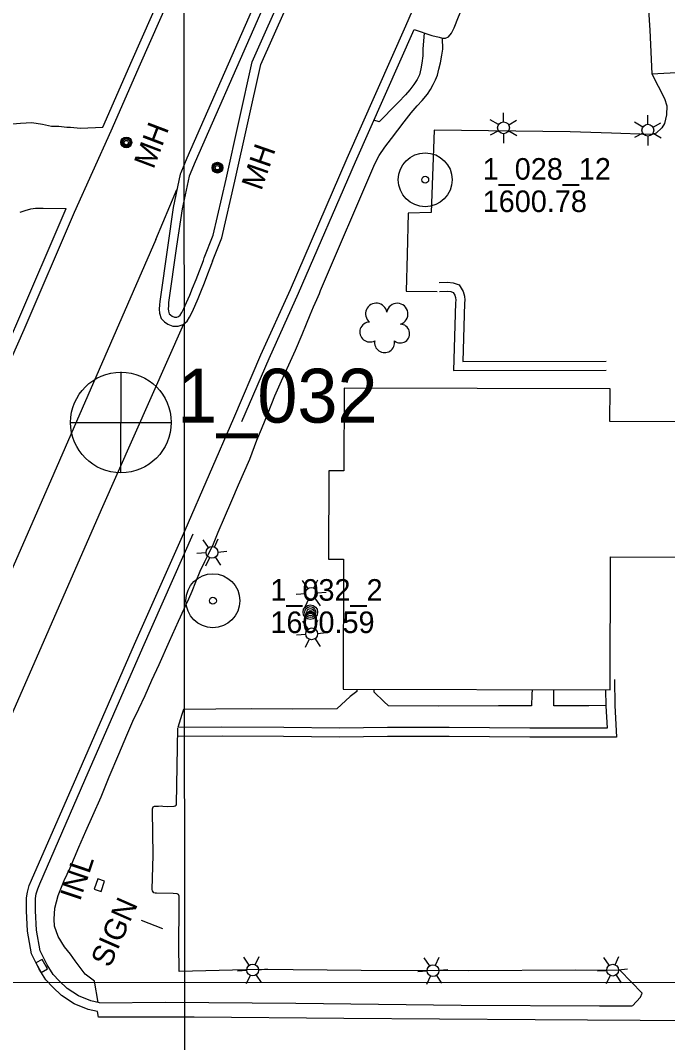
# Model space of a CAD drawing. Extents: x 189384 to 193282, y 256970 to 260388.
# Drawn here: x 190601.7 to 190781.8, y 257994.7 to 258279 of the extents above; entities that cross this region are included whole.
import ezdxf

# ---------------------------------------------------------------- set-up
doc = ezdxf.new("R2010")
doc.units = 0
for name, color, linetype in [('E_DRN_Grate', 7, 'Continuous'), ('E_DWY', 7, 'Continuous'), ('E_LAND_Vegetation', 7, 'Continuous'), ('E_MAP_GridLines', 7, 'Continuous'), ('E_MAP_Limits', 7, 'Continuous'), ('E_MAP_PassPoints', 7, 'Continuous'), ('E_MISCPROP', 7, 'Continuous'), ('E_MISCPROP_HvyLine', 7, 'Continuous'), ('E_MISCPROP_Railing', 7, 'Continuous'), ('E_PATH_Sidewalk', 7, 'Continuous'), ('E_RDWY', 7, 'Continuous')]:
    doc.layers.add(name, color=color, linetype=linetype)

# ---------------------------------------------------------------- blocks, each defined once
blk = doc.blocks.new('PP')
at = {"layer": 'E_MAP_PassPoints'}
for radius in [7.5, 0.96]:
    blk.add_circle((0, 0), radius, dxfattribs=at)
blk = doc.blocks.new('PP_2')
at = {"layer": 'E_MAP_PassPoints'}
for radius in [7.5, 0.96]:
    blk.add_circle((0, 0), radius, dxfattribs=at)
blk = doc.blocks.new('PHOTOC')
at = {"layer": 'E_MAP_Limits'}
for p, q in [((0.12, 14.06), (0.06, -13.8)), ((-13.79, 0.03), (14.12, 0.01))]:
    blk.add_line(p, q, dxfattribs=at)
blk.add_circle((0.17, 0.03), 14, dxfattribs=at)
blk = doc.blocks.new('MHO_1')
at = {"layer": 'E_DRN_Grate'}
for centre, radius in [((0.04, -0.06), 1.5), ((0.04, -0.06), 1.22), ((0.04, -0.07), 0.968), ((0.01, -0.08), 0.605)]:
    blk.add_circle(centre, radius, dxfattribs=at)
blk = doc.blocks.new('MHO_3')
at = {"layer": 'E_DRN_Grate'}
for centre, radius in [((0.04, -0.06), 1.5), ((0.04, -0.06), 1.22), ((0.04, -0.07), 0.968), ((0.01, -0.08), 0.605)]:
    blk.add_circle(centre, radius, dxfattribs=at)
blk = doc.blocks.new('LTP_6')
at = {"layer": 'E_MISCPROP'}
for p, q in [((-0.8, 1.43), (-2, 3.73)), ((0.9, 1.42), (2.27, 3.65)), ((-1.63, 0.07), (-4.24, 0.14)), ((-0.88, -1.42), (-2.24, -3.61)), ((0.76, -1.47), (2, -3.65)), ((1.64, -0.02), (4.16, -0.09))]:
    blk.add_line(p, q, dxfattribs=at)
blk.add_circle((0, 0), 1.64, dxfattribs=at)
blk = doc.blocks.new('TREE_8')
at = {"layer": 'E_LAND_Vegetation'}
for centre, radius, start, end in [((-1.47, 4.28), 2.78, 1.3947, 209.1677), ((-4.47, 0.2), 2.78, 78.0717, 279.0828), ((3.57, 2.42), 2.97, 278.4238, 139.6577), ((-2.01, -4.2), 2.61, 140.7799, 358.7125), ((3.46, -3.43), 2.97, 196.0746, 79.0479)]:
    blk.add_arc(centre, radius, start, end, dxfattribs=at)
blk = doc.blocks.new('PHOTOC_1')
at = {"layer": 'E_MAP_Limits'}
for p, q in [((0.12, 14.06), (0.06, -13.8)), ((-13.79, 0.03), (14.12, 0.01))]:
    blk.add_line(p, q, dxfattribs=at)
blk.add_circle((0.17, 0.03), 14, dxfattribs=at)
blk = doc.blocks.new('INLT_2')
at = {"layer": 'E_MISCPROP_Railing'}
blk.add_lwpolyline([(3, -2), (3, 0), (0, 0), (0, -2), (3, -2)], dxfattribs=at)
blk = doc.blocks.new('INLT_3')
at = {"layer": 'E_MISCPROP_Railing'}
blk.add_lwpolyline([(3, -2), (3, 0), (0, 0), (0, -2), (3, -2)], dxfattribs=at)
blk = doc.blocks.new('INL_3')
at = {"layer": 'E_MISCPROP_Railing'}
blk.add_text('INL', height=6, rotation=0.0001, dxfattribs=at).set_placement((-5.79, -2.75))
blk = doc.blocks.new('POLE_3')
at = {"layer": 'E_MISCPROP'}
for centre, radius in [((-0.01, 0.02), 2.02), ((-0.01, 0.03), 1.52), ((0, -0.01), 1.01), ((0, 0), 0.502)]:
    blk.add_circle(centre, radius, dxfattribs=at)
blk = doc.blocks.new('LTP_3')
at = {"layer": 'E_MISCPROP'}
for p, q in [((-0.8, 1.43), (-2, 3.73)), ((0.9, 1.42), (2.27, 3.65)), ((-1.64, 0.07), (-4.24, 0.14)), ((-0.88, -1.42), (-2.24, -3.61)), ((0.76, -1.47), (2, -3.65)), ((1.64, -0.02), (4.16, -0.09))]:
    blk.add_line(p, q, dxfattribs=at)
blk.add_circle((0, 0), 1.64, dxfattribs=at)
blk = doc.blocks.new('SIGN_3')
at = {"layer": 'E_MISCPROP'}
blk.add_text('SIGN', height=6, rotation=0.0001, dxfattribs=at).set_placement((-9.6, -3.01))

msp = doc.modelspace()

# ---------------------------------------------------------------- linework, layer by layer
at = {"layer": 'E_DWY'}
for points in [[(190711.24, 258276.48), (190716.2, 258274.86), (190718.24, 258274.36), (190719.12, 258274.13), (190719.96, 258274.1), (190720.85, 258274.5), (190721.65, 258275.48), (190722.43, 258276.98), (190723.63, 258279.98), (190730.47, 258296.26), (190731.03, 258297.66), (190732.5, 258301.06), (190732.6, 258302.29), (190732.29, 258303.32), (190731.6, 258304.03), (190730.99, 258304.56), (190730.42, 258305.08), (190725.78, 258310.13)], [(190777.42, 258264.13), (190780.95, 258257.32), (190781.61, 258255.24), (190781.5, 258252.73), (190780.93, 258250.39), (190780.22, 258249.18), (190778.63, 258247.63), (190777.7, 258247.34), (190776.69, 258247.31), (190766.21, 258247.68), (190754.67, 258248.01), (190716.82, 258248.46), (190716.02, 258225.63), (190709.55, 258225.37), (190709.29, 258213.87), (190709.07, 258203.73), (190717.67, 258203.64)], [(190571.41, 258243.16), (190582.79, 258247.78), (190585.57, 258248.49), (190588.91, 258249.27), (190592.75, 258249.91), (190595.45, 258250.07), (190598.48, 258250.18), (190601.73, 258250.45), (190604.81, 258250.59), (190607.83, 258250.14), (190610.29, 258249.63), (190612.32, 258249.6), (190614.56, 258249.35), (190615.62, 258249.32), (190618.35, 258249.03), (190624.63, 258249.31)], [(190601.57, 258225.7), (190603.01, 258226.17), (190604.57, 258226.6), (190605.85, 258226.77), (190606.82, 258226.83), (190607.51, 258226.82), (190607.95, 258226.8), (190614.38, 258226.68)], [(190718.2, 258206.15), (190720.55, 258206.25), (190722.08, 258206.04), (190723.76, 258205.45), (190724.85, 258203.66), (190725.24, 258202.36), (190725.31, 258201.21), (190725.28, 258200.4), (190724.81, 258184.15), (190764.69, 258184.27)], [(190718.3, 258203.65), (190720.43, 258203.74), (190721.49, 258203.6), (190722.09, 258203.38), (190722.55, 258202.63), (190722.76, 258201.92), (190722.81, 258201.18), (190722.78, 258200.49), (190722.24, 258181.64), (190764.7, 258181.77)], [(190766.98, 258095.69), (190767.14, 258088.47), (190767.6, 258079.68), (190743.41, 258079.62), (190721.01, 258079.82), (190703.85, 258079.82), (190690.44, 258079.64), (190674.92, 258079.86), (190657.77, 258079.94), (190645.55, 258079.8)], [(190764.54, 258092.83), (190764.64, 258088.38), (190764.96, 258082.17), (190743.42, 258082.12), (190721.02, 258082.32), (190703.84, 258082.32), (190690.44, 258082.14), (190674.94, 258082.36), (190657.76, 258082.44), (190645.52, 258082.3)], [(190772.02, 258004.91), (190774.23, 258007.32), (190774.68, 258008.42), (190768.61, 258014.78), (190756.11, 258014.88), (190726.42, 258014.7), (190696.51, 258014.76), (190668.12, 258015), (190645.85, 258014.48), (190645.75, 258022.01), (190645.86, 258032.13), (190645.82, 258035.46), (190645.62, 258035.85), (190645.33, 258036.03), (190644.19, 258036.19), (190639.58, 258036.23), (190639.16, 258036.26), (190638.78, 258036.37), (190638.46, 258036.9), (190638.35, 258037.26), (190638.61, 258046.84), (190638.41, 258059.14), (190638.45, 258059.74), (190638.63, 258060.23), (190639, 258060.43), (190639.44, 258060.49), (190640.11, 258060.5), (190640.82, 258060.51), (190641.31, 258060.48), (190642.62, 258060.35), (190644.41, 258060.42), (190644.7, 258060.51), (190645.03, 258060.75), (190645.12, 258061.06), (190645.52, 258082.2)]]:
    msp.add_lwpolyline(points, dxfattribs=at)
at = {"layer": 'E_MAP_GridLines'}
for p, q in [((190647.76, 257511.45), (190646.69, 259011.44)), ((190648.11, 257011.45), (190647.05, 258511.45)), ((189647.41, 258010.74), (191647.4, 258012.16)), ((190147.4, 258011.09), (191647.4, 258012.16))]:
    msp.add_line(p, q, dxfattribs=at)
at = {"layer": 'E_MISCPROP'}
msp.add_line((190641.34, 258026.3), (190635.4, 258028.63), dxfattribs=at)
at = {"layer": 'E_MISCPROP_HvyLine'}
msp.add_lwpolyline([(190691.47, 258093.01), (190765.78, 258092.82), (190765.87, 258129.81), (190793.45, 258129.75), (190793.55, 258167.4), (190765.75, 258167.47), (190765.77, 258176.51), (190691.75, 258176.7), (190691.69, 258153.73), (190687.5, 258153.74), (190687.44, 258129.21), (190691.57, 258129.2)], close=True, dxfattribs=at)
at = {"layer": 'E_PATH_Sidewalk'}
for points in [[(190685.22, 258203.9), (190700.32, 258239.14), (190701.47, 258241.41), (190703.08, 258243.74), (190704.94, 258246.13), (190706.69, 258248.54), (190708.46, 258250.84), (190710.41, 258253.34), (190712.09, 258255.28), (190713.52, 258256.79), (190715, 258258.54), (190715.82, 258259.78), (190716.58, 258261.16), (190717.22, 258262.52), (190717.7, 258263.82), (190718.15, 258265.47), (190718.62, 258267.26), (190718.99, 258269.33), (190719.24, 258271.01), (190719.12, 258274.13)], [(190714.04, 258275.57), (190713.67, 258271.04), (190713.66, 258269.15), (190713.4, 258267.15), (190713.15, 258265.58), (190712.71, 258263.92), (190712.11, 258262.6), (190711.2, 258261.19), (190710.06, 258259.69), (190708.82, 258258.31), (190706.87, 258256.32), (190704.71, 258254.04), (190703.2, 258252.49), (190702.39, 258251.66), (190701.87, 258251.19), (190701.75, 258251.05), (190701.52, 258250.85), (190700.06, 258251.32)], [(190623.32, 258005.87), (190622.26, 258011.76), (190619.67, 258013.76), (190618.57, 258015.21), (190616.91, 258017.4), (190615.61, 258019.32), (190613.96, 258021.34), (190612.18, 258024.2), (190611.11, 258027.12), (190611.01, 258029.05), (190611.23, 258032.09), (190612.18, 258035.61), (190613.84, 258039.81), (190615.48, 258043.3), (190617.92, 258049.07), (190619.84, 258053.52), (190621.81, 258057.89), (190624.15, 258063.08), (190626.39, 258068.66), (190629.02, 258074.88), (190631.28, 258080.25), (190632.95, 258084.08), (190634.6, 258087.53), (190636.34, 258091.2), (190638.26, 258095.47), (190640.25, 258099.82), (190643.16, 258106.39), (190645.69, 258111.95), (190647.24, 258115.33), (190647.71, 258116.36), (190648.5, 258118.16), (190649.43, 258120.26), (190650.47, 258122.84), (190651.69, 258125.79), (190652.98, 258128.5), (190654.04, 258130.54), (190655.38, 258133.47), (190656.68, 258136.67), (190658.43, 258140.75), (190660.54, 258145.52), (190662.32, 258149.86), (190665.5, 258156.99), (190667.46, 258162.29), (190668.72, 258165.35), (190670.62, 258169.9), (190672.47, 258174.61), (190674.34, 258178.81), (190676.34, 258183.22), (190678.2, 258187.31), (190680.05, 258191.66), (190681.28, 258194.6), (190682.3, 258197.15), (190682.77, 258198.28), (190683.23, 258199.31), (190684.12, 258201.42), (190684.87, 258203.1), (190685.22, 258203.9)], [(190695.3, 258093), (190695.3, 258092.34), (190693.4, 258090.93), (190689.77, 258087.55), (190677.5, 258087.48), (190665.94, 258087.52), (190656.01, 258087.44), (190647.02, 258087.33), (190646.57, 258085.97), (190645.52, 258082.3)], [(190744.07, 258092.88), (190744.01, 258091.5), (190743.94, 258088.35), (190734.77, 258088.34), (190717.94, 258088.31), (190704.15, 258088.41), (190702.83, 258089.57), (190700.14, 258092.18), (190700.13, 258092.99)], [(190764.64, 258088.48), (190759.9, 258088.4), (190750.13, 258088.39), (190750.16, 258091.81), (190750.16, 258092.86)]]:
    msp.add_lwpolyline(points, dxfattribs=at)
at = {"layer": 'E_RDWY'}
for points in [[(190616.68, 258225.7), (190626.92, 258248.31), (190635.07, 258266.98), (190648.32, 258297.01), (190666.22, 258338.37), (190675.94, 258361.41), (190677.12, 258364.96), (190677.58, 258367.44), (190677.79, 258369.25), (190677.84, 258370.35), (190676.64, 258376.89), (190675.7, 258379.42), (190674.33, 258381.46), (190672.75, 258383.67), (190670.75, 258385.6), (190668.18, 258387.61), (190665.38, 258389), (190662.69, 258390.36), (190659.88, 258391.68), (190647.05, 258398.72), (190637.72, 258402.65), (190626.82, 258407.13), (190619.98, 258409.92), (190619.19, 258407.54)], [(190624.63, 258249.31), (190632.78, 258267.99), (190646.03, 258298.02), (190663.93, 258339.35), (190673.6, 258362.29), (190674.69, 258365.58), (190675.1, 258367.82), (190675.3, 258369.45), (190675.33, 258370.17), (190674.22, 258376.22), (190673.46, 258378.27), (190672.28, 258380.04), (190670.85, 258382.03), (190669.11, 258383.71), (190666.84, 258385.48), (190664.26, 258386.76), (190661.6, 258388.12), (190658.75, 258389.45), (190645.96, 258396.47), (190636.76, 258400.34), (190625.88, 258404.82), (190619.19, 258407.54)], [(190655.15, 258212.08), (190657.73, 258218.58), (190661.37, 258234.29), (190668.54, 258266.74), (190707.08, 258353.21), (190709.49, 258358.51), (190709.98, 258360.4), (190709.94, 258361.95), (190709.15, 258363.81), (190707.97, 258364.83), (190706.07, 258365.65), (190704.5, 258365.34), (190703.21, 258364.77), (190702.47, 258363.94), (190702, 258363.33), (190701.36, 258362.46), (190687.77, 258331.38), (190664.25, 258277.63), (190647.97, 258240.66), (190646.3, 258236.67), (190646.16, 258236.23)], [(190708.95, 258277.49), (190723.47, 258311.08), (190731.29, 258330.13), (190738.5, 258348.57), (190742.07, 258358.33), (190743.07, 258360.52), (190744.03, 258362.17), (190744.95, 258363.27), (190745.84, 258364.05), (190746.7, 258364.72), (190748.34, 258365.52), (190749.54, 258365.92), (190750.87, 258366.24), (190751.94, 258366.49), (190753.53, 258366.46), (190754.66, 258366.35), (190755.63, 258366.15), (190756.81, 258365.89), (190767.32, 258362.42), (190769.01, 258361.93), (190772.39, 258360.68), (190771.52, 258358.34)], [(190652.83, 258213), (190655.33, 258219.33), (190658.93, 258234.84), (190666.15, 258267.53), (190704.8, 258354.24), (190707.13, 258359.35), (190707.47, 258360.69), (190707.45, 258361.41), (190707.08, 258362.3), (190706.63, 258362.69), (190705.8, 258363.04), (190705.25, 258362.94), (190704.71, 258362.7), (190704.4, 258362.35), (190704.01, 258361.83), (190703.54, 258361.2), (190690.06, 258330.38), (190666.54, 258276.62), (190650.27, 258239.67), (190648.61, 258235.7)], [(190776.13, 258287.7), (190776.85, 258276.31), (190777.42, 258264.13)], [(190676.79, 258204.15), (190692.6, 258240.68), (190708.95, 258277.49)], [(190679.08, 258203.16), (190694.89, 258239.67), (190711.24, 258276.48)], [(190777.42, 258264.16), (190807.79, 258265.84), (190827.61, 258267.03), (190880.57, 258269.53), (190910.27, 258270.75), (190933.63, 258272.26), (190976.88, 258274.04), (190985.13, 258274.24)], [(190646.16, 258236.23), (190644.18, 258227.02), (190642.66, 258216.55), (190640.44, 258200.88), (190640.34, 258199.89), (190640.24, 258198.69), (190640.38, 258197.61), (190640.82, 258196.12), (190641.76, 258195.19), (190642.66, 258194.51), (190644.05, 258193.99), (190645.55, 258193.99), (190646.92, 258194.44), (190648.04, 258195.41), (190648.75, 258196.48), (190649.45, 258197.84), (190650.21, 258199.56), (190651.09, 258201.63), (190651.91, 258203.56), (190652.88, 258206.06), (190653.82, 258208.5), (190654.46, 258210.19), (190654.93, 258211.41), (190655.19, 258212.19)], [(190648.61, 258235.7), (190646.64, 258226.58), (190645.14, 258216.19), (190642.92, 258200.57), (190642.83, 258199.67), (190642.76, 258198.76), (190642.84, 258198.12), (190643.03, 258197.44), (190643.4, 258197.09), (190643.88, 258196.72), (190644.5, 258196.49), (190645.15, 258196.49), (190645.66, 258196.66), (190646.15, 258197.08), (190646.6, 258197.75), (190647.19, 258198.92), (190647.91, 258200.55), (190648.79, 258202.61), (190649.59, 258204.5), (190650.55, 258206.97), (190651.49, 258209.39), (190652.12, 258211.08), (190652.58, 258212.27), (190652.83, 258213)], [(190639.31, 258218.07), (190645.21, 258231.98)], [(190486.34, 257929.3), (190500.99, 257962.31), (190519.93, 258005.2), (190540.88, 258052.68), (190557.27, 258090.57), (190575.92, 258132.39), (190589.56, 258163.44), (190602.68, 258193.06), (190616.68, 258225.7)], [(190498.7, 257963.32), (190517.65, 258006.21), (190538.59, 258053.68), (190554.98, 258091.58), (190573.63, 258133.41), (190587.27, 258164.44), (190600.39, 258194.06), (190614.38, 258226.68)], [(190639.31, 258218.07), (190609.41, 258149.39), (190580.27, 258083.06), (190547.78, 258009.13), (190519.09, 257944.03), (190494.25, 257887.28), (190465.55, 257822.08), (190442.19, 257769.07), (190419.9, 257718.5), (190394.49, 257660.93), (190374.24, 257614.8), (190349, 257556.99), (190323.12, 257498.57), (190298.43, 257442.39), (190276.94, 257393.85), (190259.86, 257355.22)], [(190647.5, 258137.19), (190661.04, 258168.43), (190668.6, 258186.03), (190676.8, 258204.19)], [(190663.33, 258167.44), (190670.89, 258185.02), (190679.08, 258203.16)], [(190647.06, 258194.52), (190624.13, 258142.92), (190594.92, 258076.29), (190570.69, 258021.28), (190551.11, 257977.35), (190533.78, 257937.86), (190511.8, 257887.72), (190488.43, 257834.81), (190463.86, 257779), (190437.37, 257718.32), (190410.84, 257658.32), (190384.1, 257597.28), (190367.03, 257558.94), (190342.84, 257503.57), (190317.05, 257445.11), (190294.43, 257394.4)], [(190623.12, 258003.35), (190620.53, 258003.93), (190616.63, 258005.47), (190613.13, 258007.77), (190610.64, 258010.1), (190608.76, 258012.12), (190606.91, 258015.08), (190604.77, 258019.43), (190603.62, 258025.68), (190603.33, 258031.32), (190603.39, 258034.96), (190603.62, 258036.57), (190604.13, 258038.35), (190604.78, 258039.88), (190617.34, 258068.71), (190633.44, 258105.56), (190647.5, 258137.19)], [(190623.66, 258005.8), (190621.26, 258006.33), (190617.79, 258007.7), (190614.68, 258009.74), (190612.41, 258011.87), (190610.75, 258013.65), (190609.1, 258016.29), (190607.16, 258020.23), (190606.11, 258025.97), (190605.83, 258031.36), (190605.89, 258034.76), (190606.07, 258036.05), (190606.49, 258037.51), (190607.07, 258038.89), (190619.63, 258067.71), (190635.73, 258104.55), (190649.78, 258136.18)], [(190816.23, 258011.98), (190816.28, 258000.29), (190788.69, 258000.79), (190744.97, 258001), (190691.66, 258001.43), (190650.06, 258001.77), (190623.43, 258001.74), (190623.12, 258003.35)], [(190623.66, 258005.8), (190641.97, 258005.93), (190678.31, 258005.7), (190724.3, 258005.15), (190762.8, 258004.92), (190771.93, 258004.91)]]:
    msp.add_lwpolyline(points, dxfattribs=at)

# ---------------------------------------------------------------- block references
at = {"layer": 'E_DRN_Grate', "xscale": 1.0000015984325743, "yscale": 1.0000015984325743, "rotation": 69.24803270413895}
msp.add_blockref('MHO_1', (190631.06, 258245.07), dxfattribs=at)
at = {"layer": 'E_DRN_Grate', "rotation": 70.86176371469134}
msp.add_blockref('MHO_3', (190656.42, 258238.04), dxfattribs=at)
at = {"layer": 'E_LAND_Vegetation', "xscale": 1.0000013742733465, "yscale": 1.0000013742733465, "rotation": 90.72455191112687}
msp.add_blockref('TREE_8', (190703.16, 258193.87), dxfattribs=at)
at = {"layer": 'E_MAP_Limits', "rotation": -0.00010367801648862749}
for name in ['PHOTOC', 'PHOTOC_1']:
    msp.add_blockref(name, (190629.46, 258167.17), dxfattribs=at)
at = {"layer": 'E_MAP_PassPoints'}
for name, p, rotation in [('PP', (190714.32, 258234.7), 0.04071592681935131), ('PP_2', (190655.23, 258117.61), -0.00010413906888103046), ('PP_2', (190655.23, 258117.61), -0.00010413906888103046)]:
    msp.add_blockref(name, p, dxfattribs=dict(at, rotation=rotation))
at = {"layer": 'E_MISCPROP'}
for name, p, rotation in [('LTP_6', (190736.13, 258249.16), 91.26330817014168), ('LTP_6', (190776.3, 258248.49), 91.26330745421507), ('LTP_3', (190654.98, 258131.04), 66.26476960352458), ('LTP_3', (190682.64, 258119.67), 66.26476911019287), ('POLE_3', (190682.37, 258114.43), 66.26476911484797), ('LTP_3', (190682.72, 258108.38), 66.26476910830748), ('SIGN_3', (190627.66, 258025.28), 66.26477008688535), ('LTP_3', (190666.31, 258014.87), 66.26476939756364), ('LTP_3', (190716.49, 258014.7), 66.26476850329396), ('LTP_3', (190766.5, 258014.86), 66.26476761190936)]:
    msp.add_blockref(name, p, dxfattribs=dict(at, rotation=rotation))
at = {"layer": 'E_MISCPROP_Railing'}
for name, p, rotation in [('INL_3', (190617.47, 258040.18), 71.44377615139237), ('INLT_3', (190622.23, 258037.38), 71.44377606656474)]:
    msp.add_blockref(name, p, dxfattribs=dict(at, rotation=rotation))
at = {"layer": 'E_MISCPROP_Railing', "xscale": 0.9999987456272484, "yscale": 0.9999987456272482, "rotation": 118.86279139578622}
msp.add_blockref('INLT_2', (190607.44, 258014.24), dxfattribs=at)

# ---------------------------------------------------------------- texts
at = {"layer": 'E_DRN_Grate'}
for rotation, p in [(69.248, (190638.7, 258237.44)), (70.8619, (190668.71, 258231.45))]:
    msp.add_text('MH', height=6, rotation=rotation, dxfattribs=at).set_placement(p)
at = {"layer": 'E_MAP_Limits'}
msp.add_text('1_032', height=15, rotation=0, dxfattribs=at).set_placement((190645.29, 258167.14))
msp.add_text('1_032', height=15, rotation=0, dxfattribs=at).set_placement((190645.29, 258167.14))
at = {"layer": 'E_MAP_PassPoints'}
for s, rotation, p in [('1_028_12', 0.0407, (190730.32, 258234.71)), ('1600.78', 0.0407, (190730.32, 258225.71)), ('1_032_2', 0, (190671.23, 258117.61)), ('1_032_2', 0, (190671.23, 258117.61)), ('1600.59', 0, (190671.23, 258108.61)), ('1600.59', 0, (190671.23, 258108.61))]:
    msp.add_text(s, height=6, rotation=rotation, dxfattribs=at).set_placement(p)

doc.saveas('drawing.dxf')
